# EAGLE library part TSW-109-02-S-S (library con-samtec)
THROUGH-HOLE .025" SQ POST HEADER Source: Samtec TSW.pdf
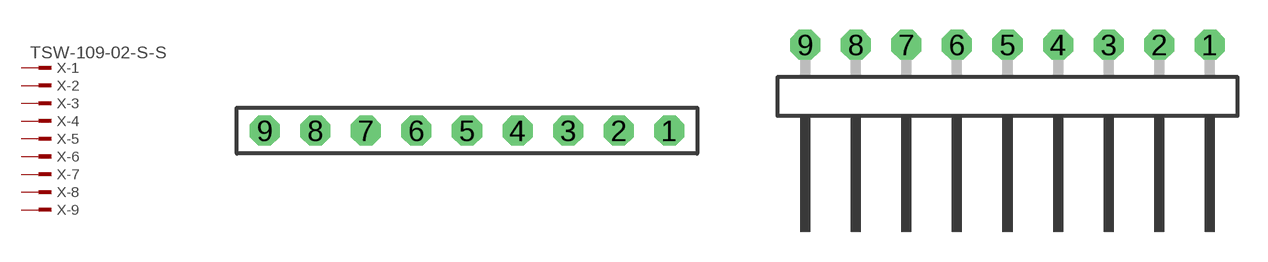
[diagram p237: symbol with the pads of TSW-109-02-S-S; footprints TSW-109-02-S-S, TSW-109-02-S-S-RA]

Designator prefix X; gates -1=MPINV -2=MPIN -3=MPIN -4=MPIN -5=MPIN -6=MPIN -7=MPIN -8=MPIN -9=MPIN

## TSW-109-02-S-S (OC_FARNELL: unknown; OC_NEWARK: unknown)  [TSW-109-02-S-S]
1  -1:1  pas
2  -2:1  pas
3  -3:1  pas
4  -4:1  pas
5  -5:1  pas
6  -6:1  pas
7  -7:1  pas
8  -8:1  pas
9  -9:1  pas

## TSW-109-02-S-S-RA (OC_FARNELL: unknown; OC_NEWARK: unknown)  [TSW-109-02-S-S-RA]
Pads as for TSW-109-02-S-S

## Footprint TSW-109-02-S-S (pad centres in mm)
THROUGH-HOLE .025" SQ POST HEADER Source: Samtec TSW.pdf
drill 1 pad 1.5 octagon: 1 10.16,0; 2 7.62,0; 3 5.08,0; 4 2.54,0; 5 0,0; 6 -2.54,0; 7 -5.08,0; 8 -7.62,0; 9 -10.16,0

## Footprint TSW-109-02-S-S-RA (pad centres in mm)
THROUGH-HOLE .025" SQ POST HEADER Source: Samtec TSW.pdf
drill 1 pad 1.5 octagon: 1 10.16,1.524; 2 7.62,1.524; 3 5.08,1.524; 4 2.54,1.524; 5 0,1.524; 6 -2.54,1.524; 7 -5.08,1.524; 8 -7.62,1.524; 9 -10.16,1.524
